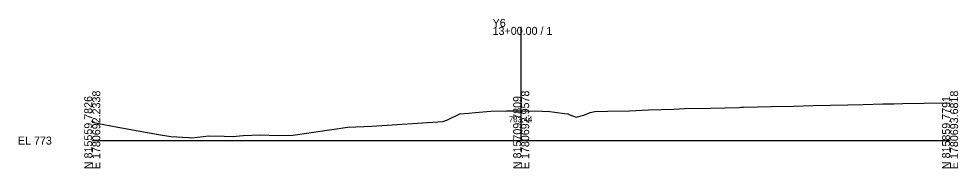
# Model space of a CAD drawing. Extents: x -26 to 1603, y -10 to 6024.
# Drawn here: x -25.7 to 302.8, y 4490.3 to 4542.7 of the extents above; entities that cross this region are included whole.
import ezdxf

# ---------------------------------------------------------------- set-up
doc = ezdxf.new("R2010")
doc.units = 0
for name, color, linetype in [('Exist Cross Section Cell', 7, 'Continuous'), ('Exist XS Center Line Elevation Label', 7, 'Continuous'), ('Exist XS Ground Line', 7, 'Continuous')]:
    doc.layers.add(name, color=color, linetype=linetype)

msp = doc.modelspace()

# ---------------------------------------------------------------- linework, layer by layer
at = {"layer": 'Exist Cross Section Cell'}
for p, q in [((150, 4500), (150, 4539.82)), ((0, 4500), (150, 4500)), ((150, 4500), (300, 4500))]:
    msp.add_line(p, q, dxfattribs=at)
at = {"layer": 'Exist XS Ground Line'}
for p, q in [((194.58, 4510.73), (203.36, 4511.05)), ((203.36, 4511.05), (207.15, 4511.18)), ((207.15, 4511.18), (216.21, 4511.39)), ((216.21, 4511.39), (226.18, 4511.63)), ((226.18, 4511.63), (226.87, 4511.65)), ((226.87, 4511.65), (227.78, 4511.68)), ((227.78, 4511.68), (237.57, 4511.94)), ((237.57, 4511.94), (245.23, 4512.09)), ((245.23, 4512.09), (252.11, 4512.25)), ((252.11, 4512.25), (264.25, 4512.53)), ((264.25, 4512.53), (269.6, 4512.66)), ((269.6, 4512.66), (276.44, 4512.81)), ((276.44, 4512.81), (280.35, 4512.89)), ((280.35, 4512.89), (283.43, 4512.96)), ((283.43, 4512.96), (290.98, 4513.15)), ((290.98, 4513.15), (300, 4513.27)), ((124, 4507.14), (128.6, 4509.4)), ((128.6, 4509.4), (131.69, 4509.61)), ((131.69, 4509.61), (133.92, 4509.8)), ((133.92, 4509.8), (139.38, 4510.27)), ((139.38, 4510.27), (144.86, 4510.37)), ((144.86, 4510.37), (149.57, 4510.45)), ((149.57, 4510.45), (150, 4510.44)), ((150, 4510.44), (157.36, 4510.28)), ((157.36, 4510.28), (160.04, 4510.23)), ((160.04, 4510.23), (161.76, 4509.97)), ((161.76, 4509.97), (165.18, 4509.51)), ((165.18, 4509.51), (166.27, 4509.32)), ((166.27, 4509.32), (167.03, 4509.06)), ((167.03, 4509.06), (169.26, 4508.15)), ((169.26, 4508.15), (171.86, 4508.95)), ((171.86, 4508.95), (174.09, 4509.81)), ((174.09, 4509.81), (175.74, 4510.24)), ((175.74, 4510.24), (180.24, 4510.26)), ((180.24, 4510.26), (187.92, 4510.4)), ((187.92, 4510.4), (194.58, 4510.73)), ((0, 4506.45), (0.54, 4506.35)), ((0.54, 4506.35), (4.01, 4505.65)), ((4.01, 4505.65), (8.93, 4504.7)), ((8.93, 4504.7), (23.2, 4502.1)), ((70.2, 4501.92), (89.38, 4504.75)), ((89.38, 4504.75), (97.75, 4505.09)), ((97.75, 4505.09), (122.55, 4506.73)), ((122.55, 4506.73), (124, 4507.14)), ((23.2, 4502.1), (27.52, 4501.38)), ((27.52, 4501.38), (33.62, 4501.05)), ((33.62, 4501.05), (34.86, 4500.99)), ((34.86, 4500.99), (40.73, 4501.68)), ((40.73, 4501.68), (46.12, 4501.52)), ((46.12, 4501.52), (49.02, 4501.47)), ((49.02, 4501.47), (52.83, 4501.81)), ((52.83, 4501.81), (58.74, 4501.98)), ((58.74, 4501.98), (64.85, 4501.75)), ((64.85, 4501.75), (70.2, 4501.92))]:
    msp.add_line(p, q, dxfattribs=at)

# ---------------------------------------------------------------- texts
at = {"layer": 'Exist Cross Section Cell'}
for s, p in [('Y6', (140, 4539.82)), ('13+00.00 / 1', (140, 4537.02)), ('EL 773', (-26, 4498.6))]:
    msp.add_text(s, height=2.8, dxfattribs=at).set_placement(p)
for s, p in [('N 815559.7826', (0, 4490)), ('E 1780692.2338', (2.8, 4490)), ('N 815709.7809', (150, 4490)), ('E 1780692.9578', (152.8, 4490)), ('N 815859.7791', (300, 4490)), ('E 1780693.6818', (302.8, 4490))]:
    msp.add_text(s, height=2.8, rotation=90, dxfattribs=at).set_placement(p)
at = {"layer": 'Exist XS Center Line Elevation Label'}
msp.add_text('783.44', height=2, dxfattribs=at).set_placement((145.72, 4506.44))

doc.saveas('drawing.dxf')
